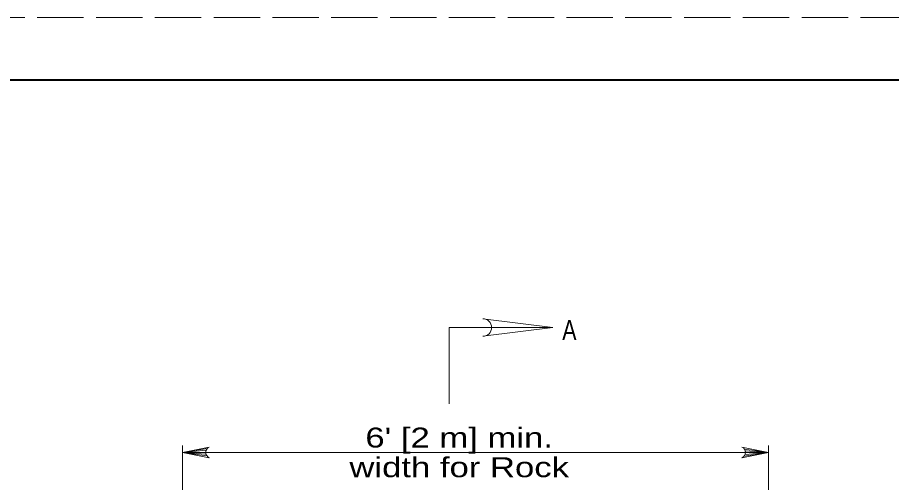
# Model space of a CAD drawing. Extents: x 1083.1 to 1117.1, y 672.5 to 716.5.
# Drawn here: x 1104.32 to 1111.34, y 712.78 to 716.51 of the extents above; entities that cross this region are included whole.
import ezdxf
from ezdxf.enums import TextEntityAlignment as Align

# ---------------------------------------------------------------- set-up
doc = ezdxf.new("R2010")
doc.units = 0
doc.header["$LTSCALE"] = 0.062
doc.linetypes.add('LONG_DASHED', pattern=[7.5, 6, -1.5])
doc.layers.add('1', color=7, linetype='Continuous', lineweight=13)
doc.layers.add('47', color=7, linetype='Continuous', lineweight=13)

msp = doc.modelspace()

# ---------------------------------------------------------------- linework, layer by layer
at = {"layer": '1', "lineweight": 25}
msp.add_line((1085.12642, 716.00825), (1116.62642, 716.00825), dxfattribs=at)
at = {"layer": '1'}
for p, q in [((1107.7885, 714.0195), (1108.62192, 714.0195)), ((1107.7885, 713.408), (1107.7885, 714.0195)), ((1105.64933, 710.7835), (1105.64933, 713.07375)), ((1110.35208, 710.97008), (1110.35208, 713.07375)), ((1105.84517, 713.04733), (1105.64933, 713.01742)), ((1105.83775, 713.03483), (1105.64933, 713.01742)), ((1110.35208, 713.01742), (1105.64933, 713.01742)), ((1105.83433, 713.01742), (1105.64933, 713.01742)), ((1105.83633, 713.00375), (1105.64933, 713.01742)), ((1105.84283, 712.99033), (1105.64933, 713.01742)), ((1105.82775, 713.01742), (1105.652, 713.01742)), ((1110.15625, 712.9875), (1110.35208, 713.01742)), ((1110.15858, 713.0445), (1110.35208, 713.01742)), ((1110.16367, 713), (1110.35208, 713.01742)), ((1110.16508, 713.03108), (1110.35208, 713.01742)), ((1110.16708, 713.01742), (1110.35208, 713.01742)), ((1110.17367, 713.01742), (1110.34942, 713.01742))]:
    msp.add_line(p, q, dxfattribs=at)
at = {"layer": '1', "linetype": 'LONG_DASHED'}
msp.add_lwpolyline([(1083.12642, 694.50825), (1117.12642, 694.50825), (1117.12642, 716.50825), (1083.12642, 716.50825)], close=True, dxfattribs=at)
at = {"layer": '1', "lineweight": 40}
msp.add_lwpolyline([(1085.12642, 716.00825), (1116.62642, 716.00825), (1116.62642, 695.00825), (1085.12642, 695.00825)], close=True, dxfattribs=at)
msp.add_lwpolyline([(1085.12642, 716.00825), (1116.62642, 716.00825), (1116.62642, 695.00825), (1085.12642, 695.00825)], close=True, dxfattribs=at)
at = {"layer": '1'}
for points in [[(1105.86308, 713.06017), (1105.64933, 713.01742), (1105.86308, 712.97467)], [(1110.13833, 712.97467), (1110.35208, 713.01742), (1110.13833, 713.06017)]]:
    msp.add_lwpolyline(points, dxfattribs=at)
for centre, start, end in [((1105.88035, 713.01735), 112.08605, 247.91218), ((1110.12109, 713.01744), 292.08605, 67.91218)]:
    msp.add_arc(centre, 0.04613, start, end, dxfattribs=at)
at = {"layer": '47'}
msp.add_lwpolyline([(1108.05942, 714.08975), (1108.62192, 714.0195), (1108.05942, 713.94925)], dxfattribs=at)
msp.add_arc((1108.0594, 714.01948), 0.07025, 270, 90, dxfattribs=at)

# ---------------------------------------------------------------- texts
at = {"layer": '1', "width": 0.8}
msp.add_text('A', height=0.16, dxfattribs=at).set_placement((1108.6965, 713.91992))
at = {"layer": '1', "width": 1.3}
for s, p in [("6' [2 m] min.", (1107.86892, 713.05633)), ('width for Rock', (1107.86892, 712.81833))]:
    msp.add_text(s, height=0.16, dxfattribs=at).set_placement(p, align=Align.CENTER)

doc.saveas('drawing.dxf')
